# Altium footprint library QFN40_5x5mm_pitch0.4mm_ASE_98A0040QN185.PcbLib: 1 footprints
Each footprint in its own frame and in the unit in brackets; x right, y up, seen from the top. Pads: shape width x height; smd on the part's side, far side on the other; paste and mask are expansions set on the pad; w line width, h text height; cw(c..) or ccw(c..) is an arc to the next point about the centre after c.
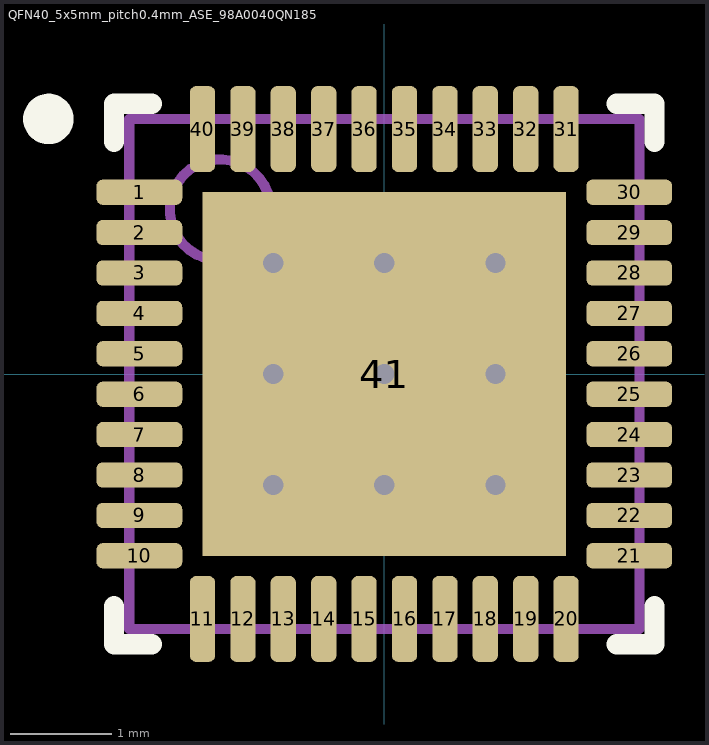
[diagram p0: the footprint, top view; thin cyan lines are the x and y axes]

## QFN40_5x5mm_pitch0.4mm_ASE_98A0040QN185 [mm] "QFN40 body 5x5mm pitch 0.4mm Manufacturer ASE"
height 0.75
pads (41):
  rrect50% 0.85x0.25 smd: 1(-2.425,1.8) 2(-2.425,1.4) 3(-2.425,1) 4(-2.425,0.6) 5(-2.425,0.2) 6(-2.425,-0.2) 7(-2.425,-0.6) 8(-2.425,-1) 9(-2.425,-1.4) 10(-2.425,-1.8) 21(2.425,-1.8) 22(2.425,-1.4) 23(2.425,-1) 24(2.425,-0.6) 25(2.425,-0.2) 26(2.425,0.2) 27(2.425,0.6) 28(2.425,1) 29(2.425,1.4) 30(2.425,1.8)
  rrect50% 0.25x0.85 smd: 11(-1.8,-2.425) 12(-1.4,-2.425) 13(-1,-2.425) 14(-0.6,-2.425) 15(-0.2,-2.425) 16(0.2,-2.425) 17(0.6,-2.425) 18(1,-2.425) 19(1.4,-2.425) 20(1.8,-2.425) 31(1.8,2.425) 32(1.4,2.425) 33(1,2.425) 34(0.6,2.425) 35(0.2,2.425) 36(-0.2,2.425) 37(-0.6,2.425) 38(-1,2.425) 39(-1.4,2.425) 40(-1.8,2.425)
  rect 3.6x3.6 smd: 41(0,0)
via -1.1,1.1 diameter 0.5 hole 0.2
via 0,1.1 diameter 0.5 hole 0.2
via 1.1,1.1 diameter 0.5 hole 0.2
via -1.1,0 diameter 0.5 hole 0.2
via 0,0 diameter 0.5 hole 0.2
via 1.1,0 diameter 0.5 hole 0.2
via -1.1,-1.1 diameter 0.5 hole 0.2
via 0,-1.1 diameter 0.5 hole 0.2
via 1.1,-1.1 diameter 0.5 hole 0.2
Top Overlay:
  circle w0.25: c-3.325,2.525 r0.125
  lines w0.2: -2.675,-2.3 -2.675,-2.675 -2.3,-2.675 ; -2.675,2.3 -2.675,2.675 -2.3,2.675 ; 2.3,-2.675 2.675,-2.675 2.675,-2.3 ; 2.3,2.675 2.675,2.675 2.675,2.3
Mechanical 13:
  circle w0.1: c-1.625,1.625 r0.5
  lines w0.1: -2.525,-2.525 -2.525,2.525 2.525,2.525 2.525,-2.525 -2.525,-2.525
3D body "QFN40P500X500X90_HS-41N.step": height 1, standoff 0.1, extent -2.551,-2.551 2.551,2.551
